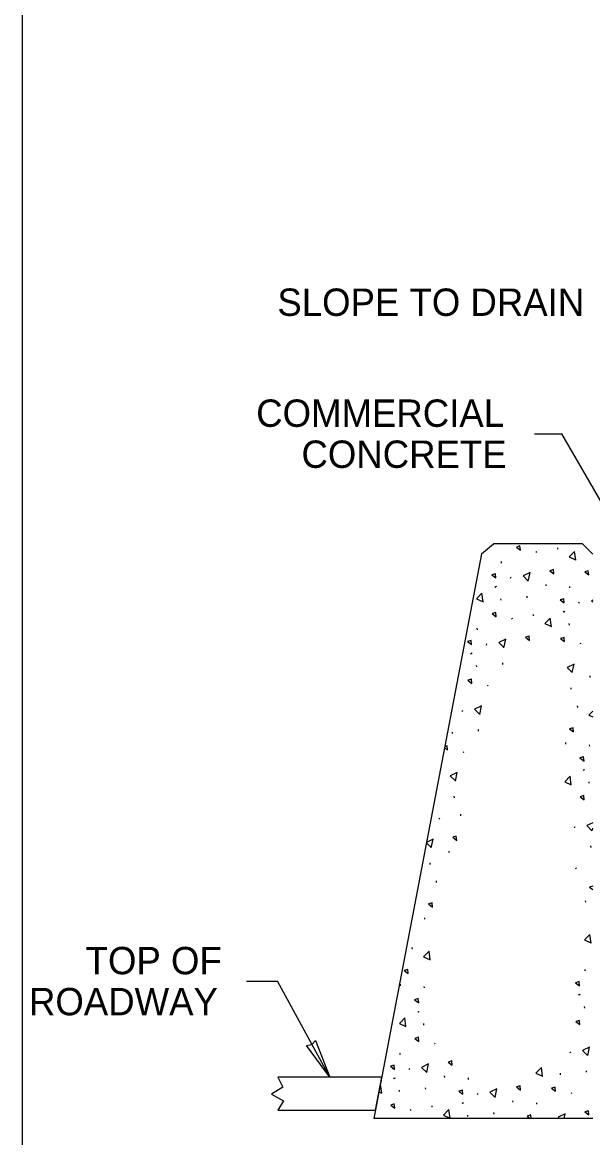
# Model space of a CAD drawing. Extents: x 99862 to 103151, y 100000 to 102076.
# Drawn here: x 99862 to 100196, y 100477 to 101130 of the extents above; entities that cross this region are included whole.
import ezdxf

# ---------------------------------------------------------------- set-up
doc = ezdxf.new("R2010")
doc.units = 0
for name, color, linetype in [('Level 1', 7, 'Continuous'), ('Level 13', 7, 'Continuous'), ('Level 15', 7, 'Continuous'), ('Level 2', 7, 'Continuous'), ('Level 20', 7, 'Continuous'), ('Level 49', 7, 'Continuous')]:
    doc.layers.add(name, color=color, linetype=linetype)

msp = doc.modelspace()

# ---------------------------------------------------------------- linework, layer by layer
at = {"layer": 'Level 1'}
msp.add_lwpolyline([(99862, 99999.5), (103151, 99999.5), (103151, 102075.5), (99862, 102075.5)], close=True, dxfattribs=at)
at = {"layer": 'Level 13'}
for p, q in [((100175.33, 100821.53), (100175.27, 100822.4)), ((100162.95, 100819.99), (100162.44, 100819.61)), ((100142.4, 100813.39), (100142.34, 100814.26)), ((100147.84, 100805.16), (100147.49, 100804.44)), ((100138.99, 100799.58), (100138.47, 100799.2)), ((100139.39, 100799.65), (100138.87, 100799.27)), ((100168.45, 100800.03), (100168.39, 100800.91)), ((100182.38, 100798.84), (100182.32, 100799.71)), ((100142.06, 100791.67), (100142, 100792.54)), ((100157.33, 100793.12), (100157.27, 100793.99)), ((100187.82, 100790.61), (100187.46, 100789.89)), ((100161.14, 100782.55), (100161.08, 100783.42)), ((100178.96, 100785.03), (100178.44, 100784.65)), ((100179.36, 100785.1), (100178.85, 100784.72)), ((100148.77, 100781.01), (100148.25, 100780.63)), ((100182.03, 100777.12), (100181.97, 100777.99)), ((100128.22, 100774.41), (100128.16, 100775.28)), ((100133.66, 100766.18), (100133.3, 100765.46)), ((100188.74, 100766.46), (100188.22, 100766.08)), ((100124.8, 100760.6), (100124.28, 100760.22)), ((100125.2, 100760.67), (100124.69, 100760.29)), ((100127.87, 100752.69), (100127.81, 100753.56)), ((100143.14, 100754.14), (100143.08, 100755.01)), ((100194.23, 100746.5), (100194.17, 100747.38)), ((100134.58, 100742.03), (100134.06, 100741.65)), ((100183.12, 100739.59), (100183.05, 100740.46)), ((100186.92, 100729.02), (100186.86, 100729.9)), ((100119.47, 100727.2), (100119.11, 100726.48)), ((100113.69, 100713.71), (100113.63, 100714.58)), ((100128.96, 100715.16), (100128.9, 100716.03)), ((100180.04, 100707.52), (100179.98, 100708.4)), ((100193.97, 100706.33), (100193.91, 100707.2)), ((100120.39, 100703.05), (100119.87, 100702.67)), ((100190.56, 100692.52), (100190.04, 100692.14)), ((100190.96, 100692.59), (100190.44, 100692.21)), ((100193.63, 100684.61), (100193.57, 100685.48)), ((100114.77, 100676.18), (100114.71, 100677.05)), ((100118.58, 100665.61), (100118.52, 100666.49)), ((100106.2, 100664.07), (100105.69, 100663.69)), ((100185.23, 100659.12), (100184.87, 100658.4)), ((100194.71, 100647.08), (100194.65, 100647.95)), ((100111.7, 100644.11), (100111.64, 100644.99)), ((100100.58, 100637.2), (100100.52, 100638.07)), ((100186.15, 100634.97), (100185.63, 100634.59)), ((100104.39, 100626.63), (100104.33, 100627.51)), ((100191.64, 100615.02), (100191.58, 100615.89)), ((100097.51, 100605.13), (100097.45, 100606.01)), ((100090.2, 100587.65), (100090.14, 100588.53)), ((100191.38, 100574.84), (100191.32, 100575.71)), ((100083.32, 100566.15), (100083.26, 100567.03)), ((100097.25, 100564.96), (100097.19, 100565.83)), ((100187.96, 100561.03), (100187.45, 100560.65)), ((100188.37, 100561.1), (100187.85, 100560.72)), ((100191.04, 100553.12), (100190.98, 100554)), ((100093.83, 100551.15), (100093.32, 100550.77)), ((100094.24, 100551.22), (100093.72, 100550.84)), ((100096.91, 100543.24), (100096.85, 100544.11)), ((100103.61, 100532.58), (100103.1, 100532.2)), ((100182.64, 100527.63), (100182.28, 100526.91)), ((100083.06, 100525.98), (100083, 100526.85)), ((100088.5, 100517.75), (100088.15, 100517.03)), ((100176.85, 100514.14), (100176.79, 100515.02)), ((100192.12, 100515.59), (100192.06, 100516.46)), ((100079.65, 100512.17), (100079.13, 100511.79)), ((100080.05, 100512.24), (100079.53, 100511.86)), ((100109.11, 100512.63), (100109.05, 100513.5)), ((100123.04, 100511.43), (100122.98, 100512.3)), ((100082.72, 100504.26), (100082.66, 100505.13)), ((100097.99, 100505.71), (100097.93, 100506.58)), ((100128.48, 100503.2), (100128.12, 100502.48)), ((100183.56, 100503.48), (100183.04, 100503.1)), ((100101.8, 100495.14), (100101.74, 100496.02)), ((100119.62, 100497.62), (100119.1, 100497.24)), ((100120.02, 100497.69), (100119.5, 100497.31)), ((100149.08, 100498.08), (100149.02, 100498.95)), ((100163.01, 100496.88), (100162.95, 100497.75)), ((100089.42, 100493.6), (100088.91, 100493.22)), ((100122.69, 100489.71), (100122.63, 100490.59)), ((100137.96, 100491.16), (100137.9, 100492.03)), ((100168.45, 100488.65), (100168.44, 100488.64))]:
    msp.add_line(p, q, dxfattribs=at)
for points in [[(100153.4, 100821.01), (100153.16, 100823.46), (100151.03, 100822.81), (100153.4, 100821.01)], [(100185.77, 100815.18), (100185.07, 100820.25), (100181.89, 100816.97), (100185.69, 100815.21)], [(100172.91, 100807.15), (100172.67, 100809.6), (100170.54, 100808.96), (100172.91, 100807.15)], [(100193.37, 100806.46), (100193.13, 100808.91), (100191.01, 100808.26), (100193.37, 100806.46)], [(100139.05, 100804.69), (100138.81, 100807.14), (100136.68, 100806.49), (100139.05, 100804.69)], [(100157.98, 100802.86), (100159.06, 100807.87), (100154.94, 100805.88), (100157.91, 100802.92)], [(100131.61, 100790.75), (100130.91, 100795.82), (100127.73, 100792.54), (100131.53, 100790.78)], [(100179.02, 100790.14), (100178.78, 100792.59), (100176.65, 100791.94), (100179.02, 100790.14)], [(100195.7, 100791.71), (100194.92, 100791.33), (100195.7, 100790.55)], [(100139.21, 100782.03), (100138.97, 100784.48), (100136.85, 100783.83), (100139.21, 100782.03)], [(100171.58, 100776.2), (100170.88, 100781.27), (100167.7, 100777.99), (100171.5, 100776.23)], [(100158.72, 100768.17), (100158.48, 100770.62), (100156.36, 100769.98), (100158.72, 100768.17)], [(100179.19, 100767.48), (100178.94, 100769.93), (100176.82, 100769.29), (100179.19, 100767.48)], [(100124.86, 100765.71), (100124.62, 100768.16), (100122.49, 100767.51), (100124.86, 100765.71)], [(100143.79, 100763.88), (100144.87, 100768.89), (100140.76, 100766.9), (100143.73, 100763.94)], [(100183.77, 100749.34), (100184.84, 100754.35), (100180.73, 100752.35), (100183.7, 100749.39)], [(100125.03, 100743.05), (100124.78, 100745.5), (100122.66, 100744.85), (100125.03, 100743.05)], [(100129.61, 100724.9), (100130.68, 100729.91), (100126.57, 100727.92), (100129.54, 100724.96)], [(100195.7, 100726.75), (100193.49, 100724.46), (100195.7, 100723.44)], [(100184.51, 100714.64), (100184.26, 100717.09), (100182.14, 100716.45), (100184.51, 100714.64)], [(100109, 100705.47), (100110.84, 100704.07)], [(100110.84, 100704.07), (100110.6, 100706.52), (100109.12, 100706.07)], [(100190.62, 100697.63), (100190.38, 100700.08), (100188.25, 100699.43), (100190.62, 100697.63)], [(100115.42, 100685.92), (100116.49, 100690.94), (100112.38, 100688.94), (100115.35, 100685.98)], [(100183.18, 100683.69), (100182.48, 100688.77), (100179.3, 100685.48), (100183.1, 100683.72)], [(100190.78, 100674.97), (100190.54, 100677.42), (100188.42, 100676.78), (100190.78, 100674.97)], [(100195.7, 100661.48), (100192.33, 100659.84), (100195.29, 100656.88)], [(100195.36, 100656.83), (100195.7, 100658.4)], [(100101.23, 100646.94), (100102.31, 100651.96), (100098.45, 100650.08)], [(100116.16, 100651.23), (100115.92, 100653.68), (100113.79, 100653.04), (100116.16, 100651.23)], [(100098.39, 100649.76), (100101.16, 100647)], [(100195.7, 100624.54), (100193.74, 100623.94), (100195.7, 100622.44)], [(100101.97, 100612.25), (100101.73, 100614.7), (100099.61, 100614.06), (100101.97, 100612.25)], [(100194.78, 100591.18), (100194.08, 100596.26), (100190.9, 100592.97), (100194.7, 100591.21)], [(100100.65, 100581.3), (100099.94, 100586.38), (100096.76, 100583.09), (100100.56, 100581.33)], [(100087.78, 100573.27), (100087.54, 100575.72), (100085.42, 100575.08), (100087.78, 100573.27)], [(100188.03, 100566.14), (100187.79, 100568.59), (100185.66, 100567.95), (100188.03, 100566.14)], [(100093.9, 100556.26), (100093.65, 100558.71), (100091.53, 100558.06), (100093.9, 100556.26)], [(100086.46, 100542.32), (100085.76, 100547.4), (100082.58, 100544.11), (100086.38, 100542.35)], [(100188.19, 100543.48), (100187.95, 100545.93), (100185.83, 100545.29), (100188.19, 100543.48)], [(100094.06, 100533.6), (100093.82, 100536.05), (100091.69, 100535.41), (100094.06, 100533.6)], [(100192.77, 100525.34), (100193.85, 100530.35), (100189.74, 100528.35), (100192.7, 100525.4)], [(100113.57, 100519.74), (100113.33, 100522.19), (100111.2, 100521.55), (100113.57, 100519.74)], [(100079.71, 100517.28), (100079.47, 100519.73), (100077.34, 100519.08), (100079.71, 100517.28)], [(100098.64, 100515.46), (100099.72, 100520.47), (100095.6, 100518.47), (100098.57, 100515.51)], [(100166.4, 100513.22), (100165.7, 100518.3), (100162.52, 100515.01), (100166.32, 100513.25)], [(100072.27, 100503.34), (100071.57, 100508.42), (100071.44, 100508.29)], [(100070.64, 100504.09), (100072.19, 100503.37)], [(100119.68, 100502.73), (100119.44, 100505.18), (100117.31, 100504.54), (100119.68, 100502.73)], [(100138.61, 100500.91), (100139.69, 100505.92), (100135.58, 100503.92), (100138.54, 100500.96)], [(100153.54, 100505.2), (100153.3, 100507.65), (100151.18, 100507), (100153.54, 100505.2)], [(100174.01, 100504.5), (100173.76, 100506.95), (100171.64, 100506.31), (100174.01, 100504.5)], [(100079.87, 100494.62), (100079.63, 100497.07), (100077.51, 100496.43), (100079.87, 100494.62)], [(100112.24, 100488.79), (100111.54, 100493.87), (100108.36, 100490.58), (100112.16, 100488.82)], [(100159.61, 100488.64), (100159.41, 100490.63), (100157.29, 100489.99), (100159.05, 100488.64)], [(100179.07, 100488.64), (100179.66, 100491.37), (100175.55, 100489.37), (100176.29, 100488.64)], [(100193.51, 100490.65), (100193.27, 100493.1), (100191.15, 100492.45), (100193.51, 100490.65)]]:
    msp.add_lwpolyline(points, dxfattribs=at)
at = {"layer": 'Level 15'}
for p, q in [((100161.58, 100889.08), (100177.58, 100889.08)), ((100217.99, 100819.08), (100177.58, 100889.08)), ((99993.25, 100568.93), (100011.21, 100568.93)), ((100041.89, 100512.64), (100011.21, 100568.93))]:
    msp.add_line(p, q, dxfattribs=at)
msp.add_lwpolyline([(100041.89, 100512.64), (100028.34, 100531.25), (100031.47, 100531.76), (100033.58, 100534.11)], close=True, dxfattribs=at)
at = {"layer": 'Level 2'}
for p, q in [((100130.58, 100818.74), (100134.14, 100821.69)), ((100134.14, 100821.69), (100137.7, 100824.64)), ((100189.7, 100824.64), (100137.7, 100824.64)), ((100189.7, 100824.64), (100195.7, 100818.64)), ((100130.58, 100818.74), (100067.7, 100488.64)), ((100195.7, 100488.64), (100067.7, 100488.64))]:
    msp.add_line(p, q, dxfattribs=at)
at = {"layer": 'Level 49'}
for p, q in [((100072.27, 100512.64), (100011.5, 100512.64)), ((100011.5, 100512.64), (100014.5, 100506.96)), ((100068.61, 100493.44), (100072.27, 100512.64)), ((100014.5, 100506.96), (100007.7, 100502.82)), ((100007.7, 100502.82), (100014.9, 100498.82)), ((100014.9, 100498.82), (100011.5, 100493.44)), ((100011.5, 100493.44), (100068.61, 100493.44))]:
    msp.add_line(p, q, dxfattribs=at)

# ---------------------------------------------------------------- texts
at = {"layer": 'Level 20'}
for s, p in [('SLOPE TO DRAIN', (100011.22, 100957.99)), ('COMMERCIAL', (99998.84, 100893.09)), ('CONCRETE', (100025.32, 100869.09)), ('TOP OF', (99899.06, 100572.93)), ('ROADWAY', (99865.9, 100548.93))]:
    msp.add_text(s, height=16, dxfattribs=at).set_placement(p)

doc.saveas('drawing.dxf')
